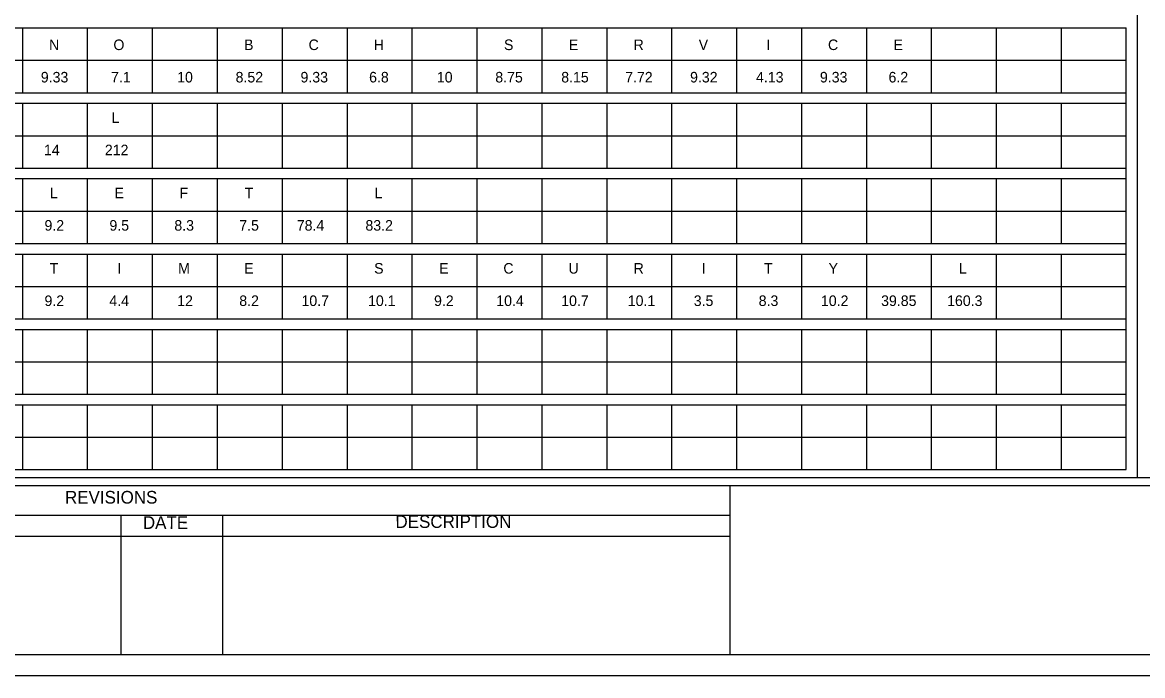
# Model space of a CAD drawing. Extents: x 17890628 to 17890817, y 17897493 to 17897992.
# Drawn here: x 17890684.6 to 17890736.6, y 17897492.8 to 17897523.1 of the extents above; entities that cross this region are included whole.
import ezdxf

# ---------------------------------------------------------------- set-up
doc = ezdxf.new("R2010")
doc.units = 0
for name, color, linetype in [('GSSign', 7, 'Continuous'), ('PlotBorder_dp', 7, 'Continuous'), ('SheetBorder_dp', 7, 'Continuous'), ('SheetLines_dp', 7, 'Continuous'), ('SheetLinesMisc2_dp', 7, 'Continuous'), ('TextMisc', 7, 'Continuous')]:
    doc.layers.add(name, color=color, linetype=linetype)

msp = doc.modelspace()

# ---------------------------------------------------------------- linework, layer by layer
at = {"layer": 'PlotBorder_dp'}
msp.add_lwpolyline([(17890655.57, 17897492.839), (17890817.319, 17897492.839), (17890817.319, 17897596.75), (17890655.57, 17897596.75)], close=True, dxfattribs=at)
at = {"layer": 'SheetBorder_dp'}
for p, q in [((17890660.962, 17897501.661), (17890811.928, 17897501.661)), ((17890660.962, 17897493.819), (17890811.928, 17897493.819))]:
    msp.add_line(p, q, dxfattribs=at)
at = {"layer": 'SheetLines_dp'}
for p, q in [((17890717.427, 17897501.661), (17890717.427, 17897493.819)), ((17890660.962, 17897500.289), (17890717.427, 17897500.289)), ((17890689.194, 17897500.289), (17890689.194, 17897493.819)), ((17890693.9, 17897500.289), (17890693.9, 17897493.819)), ((17890660.962, 17897499.309), (17890717.427, 17897499.309))]:
    msp.add_line(p, q, dxfattribs=at)
at = {"layer": 'SheetLinesMisc2_dp'}
for p, q in [((17890736.311, 17897595.691), (17890736.311, 17897502.033)), ((17890661.804, 17897522.886), (17890735.8, 17897522.886)), ((17890684.628, 17897522.886), (17890684.628, 17897519.88)), ((17890687.638, 17897522.886), (17890687.638, 17897519.88)), ((17890690.648, 17897522.886), (17890690.648, 17897519.88)), ((17890693.658, 17897522.886), (17890693.658, 17897519.88)), ((17890696.669, 17897522.886), (17890696.669, 17897519.88)), ((17890699.679, 17897522.886), (17890699.679, 17897519.88)), ((17890702.689, 17897522.886), (17890702.689, 17897519.88)), ((17890705.699, 17897522.886), (17890705.699, 17897519.88)), ((17890708.709, 17897522.886), (17890708.709, 17897519.88)), ((17890711.719, 17897522.886), (17890711.719, 17897519.88)), ((17890714.729, 17897522.886), (17890714.729, 17897519.88)), ((17890717.739, 17897522.886), (17890717.739, 17897519.88)), ((17890720.749, 17897522.886), (17890720.749, 17897519.88)), ((17890723.759, 17897522.886), (17890723.759, 17897519.88)), ((17890726.769, 17897522.886), (17890726.769, 17897519.88)), ((17890729.779, 17897522.886), (17890729.779, 17897519.88)), ((17890732.79, 17897522.886), (17890732.79, 17897519.88)), ((17890735.8, 17897502.398), (17890735.8, 17897522.886)), ((17890661.804, 17897521.384), (17890735.8, 17897521.384)), ((17890661.804, 17897519.88), (17890735.8, 17897519.88)), ((17890661.804, 17897519.389), (17890735.8, 17897519.389)), ((17890684.628, 17897519.389), (17890684.628, 17897516.383)), ((17890687.638, 17897519.389), (17890687.638, 17897516.383)), ((17890690.648, 17897519.389), (17890690.648, 17897516.383)), ((17890693.658, 17897519.389), (17890693.658, 17897516.383)), ((17890696.669, 17897519.389), (17890696.669, 17897516.383)), ((17890699.679, 17897519.389), (17890699.679, 17897516.383)), ((17890702.689, 17897519.389), (17890702.689, 17897516.383)), ((17890705.699, 17897519.389), (17890705.699, 17897516.383)), ((17890708.709, 17897519.389), (17890708.709, 17897516.383)), ((17890711.719, 17897519.389), (17890711.719, 17897516.383)), ((17890714.729, 17897519.389), (17890714.729, 17897516.383)), ((17890717.739, 17897519.389), (17890717.739, 17897516.383)), ((17890720.749, 17897519.389), (17890720.749, 17897516.383)), ((17890723.759, 17897519.389), (17890723.759, 17897516.383)), ((17890726.769, 17897519.389), (17890726.769, 17897516.383)), ((17890729.779, 17897519.389), (17890729.779, 17897516.383)), ((17890732.79, 17897519.389), (17890732.79, 17897516.383)), ((17890661.804, 17897517.886), (17890735.8, 17897517.886)), ((17890661.804, 17897516.383), (17890735.8, 17897516.383)), ((17890661.804, 17897515.893), (17890735.8, 17897515.893)), ((17890684.628, 17897515.893), (17890684.628, 17897512.887)), ((17890687.638, 17897515.893), (17890687.638, 17897512.887)), ((17890690.648, 17897515.893), (17890690.648, 17897512.887)), ((17890693.658, 17897515.893), (17890693.658, 17897512.887)), ((17890696.669, 17897515.893), (17890696.669, 17897512.887)), ((17890699.679, 17897515.893), (17890699.679, 17897512.887)), ((17890702.689, 17897515.893), (17890702.689, 17897512.887)), ((17890705.699, 17897515.893), (17890705.699, 17897512.887)), ((17890708.709, 17897515.893), (17890708.709, 17897512.887)), ((17890711.719, 17897515.893), (17890711.719, 17897512.887)), ((17890714.729, 17897515.893), (17890714.729, 17897512.887)), ((17890717.739, 17897515.893), (17890717.739, 17897512.887)), ((17890720.749, 17897515.893), (17890720.749, 17897512.887)), ((17890723.759, 17897515.893), (17890723.759, 17897512.887)), ((17890726.769, 17897515.893), (17890726.769, 17897512.887)), ((17890729.779, 17897515.893), (17890729.779, 17897512.887)), ((17890732.79, 17897515.893), (17890732.79, 17897512.887)), ((17890661.804, 17897514.39), (17890735.8, 17897514.39)), ((17890661.804, 17897512.887), (17890735.8, 17897512.887)), ((17890661.804, 17897512.396), (17890735.8, 17897512.396)), ((17890684.628, 17897512.396), (17890684.628, 17897509.39)), ((17890687.638, 17897512.396), (17890687.638, 17897509.39)), ((17890690.648, 17897512.396), (17890690.648, 17897509.39)), ((17890693.658, 17897512.396), (17890693.658, 17897509.39)), ((17890696.669, 17897512.396), (17890696.669, 17897509.39)), ((17890699.679, 17897512.396), (17890699.679, 17897509.39)), ((17890702.689, 17897512.396), (17890702.689, 17897509.39)), ((17890705.699, 17897512.396), (17890705.699, 17897509.39)), ((17890708.709, 17897512.396), (17890708.709, 17897509.39)), ((17890711.719, 17897512.396), (17890711.719, 17897509.39)), ((17890714.729, 17897512.396), (17890714.729, 17897509.39)), ((17890717.739, 17897512.396), (17890717.739, 17897509.39)), ((17890720.749, 17897512.396), (17890720.749, 17897509.39)), ((17890723.759, 17897512.396), (17890723.759, 17897509.39)), ((17890726.769, 17897512.396), (17890726.769, 17897509.39)), ((17890729.779, 17897512.396), (17890729.779, 17897509.39)), ((17890732.79, 17897512.396), (17890732.79, 17897509.39)), ((17890661.804, 17897510.894), (17890735.8, 17897510.894)), ((17890661.804, 17897509.39), (17890735.8, 17897509.39)), ((17890661.804, 17897508.9), (17890735.8, 17897508.9)), ((17890684.628, 17897508.9), (17890684.628, 17897505.894)), ((17890687.638, 17897508.9), (17890687.638, 17897505.894)), ((17890690.648, 17897508.9), (17890690.648, 17897505.894)), ((17890693.658, 17897508.9), (17890693.658, 17897505.894)), ((17890696.669, 17897508.9), (17890696.669, 17897505.894)), ((17890699.679, 17897508.9), (17890699.679, 17897505.894)), ((17890702.689, 17897508.9), (17890702.689, 17897505.894)), ((17890705.699, 17897508.9), (17890705.699, 17897505.894)), ((17890708.709, 17897508.9), (17890708.709, 17897505.894)), ((17890711.719, 17897508.9), (17890711.719, 17897505.894)), ((17890714.729, 17897508.9), (17890714.729, 17897505.894)), ((17890717.739, 17897508.9), (17890717.739, 17897505.894)), ((17890720.749, 17897508.9), (17890720.749, 17897505.894)), ((17890723.759, 17897508.9), (17890723.759, 17897505.894)), ((17890726.769, 17897508.9), (17890726.769, 17897505.894)), ((17890729.779, 17897508.9), (17890729.779, 17897505.894)), ((17890732.79, 17897508.9), (17890732.79, 17897505.894)), ((17890661.804, 17897507.396), (17890735.8, 17897507.396)), ((17890661.804, 17897505.894), (17890735.8, 17897505.894)), ((17890661.804, 17897505.403), (17890735.8, 17897505.403)), ((17890684.628, 17897505.403), (17890684.628, 17897502.398)), ((17890687.638, 17897505.403), (17890687.638, 17897502.398)), ((17890690.648, 17897505.403), (17890690.648, 17897502.398)), ((17890693.658, 17897505.403), (17890693.658, 17897502.398)), ((17890696.669, 17897505.403), (17890696.669, 17897502.398)), ((17890699.679, 17897505.403), (17890699.679, 17897502.398)), ((17890702.689, 17897505.403), (17890702.689, 17897502.398)), ((17890705.699, 17897505.403), (17890705.699, 17897502.398)), ((17890708.709, 17897505.403), (17890708.709, 17897502.398)), ((17890711.719, 17897505.403), (17890711.719, 17897502.398)), ((17890714.729, 17897505.403), (17890714.729, 17897502.398)), ((17890717.739, 17897505.403), (17890717.739, 17897502.398)), ((17890720.749, 17897505.403), (17890720.749, 17897502.398)), ((17890723.759, 17897505.403), (17890723.759, 17897502.398)), ((17890726.769, 17897505.403), (17890726.769, 17897502.398)), ((17890729.779, 17897505.403), (17890729.779, 17897502.398)), ((17890732.79, 17897505.403), (17890732.79, 17897502.398)), ((17890661.804, 17897503.9), (17890735.8, 17897503.9)), ((17890661.804, 17897502.398), (17890735.8, 17897502.398)), ((17890661.083, 17897502.033), (17890811.539, 17897502.033))]:
    msp.add_line(p, q, dxfattribs=at)

# ---------------------------------------------------------------- texts
at = {"layer": 'GSSign'}
for s, height, p in [('N', 0.49, (17890685.865, 17897521.859)), ('O', 0.49, (17890688.848, 17897521.859)), ('B', 0.49, (17890694.904, 17897521.859)), ('C', 0.49, (17890697.898, 17897521.859)), ('H', 0.49, (17890700.917, 17897521.859)), ('S', 0.49, (17890706.958, 17897521.859)), ('E', 0.49, (17890709.968, 17897521.859)), ('R', 0.49, (17890712.966, 17897521.859)), ('V', 0.49, (17890715.986, 17897521.859)), ('I', 0.49, (17890719.13, 17897521.859)), ('C', 0.49, (17890721.981, 17897521.859)), ('E', 0.49, (17890725.019, 17897521.859)), ('9.33', 0.4902, (17890685.482, 17897520.356)), ('7.1', 0.4902, (17890688.737, 17897520.356)), ('10', 0.4902, (17890691.803, 17897520.356)), ('8.52', 0.4902, (17890694.513, 17897520.356)), ('9.33', 0.4902, (17890697.523, 17897520.356)), ('6.8', 0.4902, (17890700.703, 17897520.356)), ('10', 0.4902, (17890703.845, 17897520.356)), ('8.75', 0.4902, (17890706.554, 17897520.356)), ('8.15', 0.4902, (17890709.612, 17897520.356)), ('7.72', 0.4902, (17890712.575, 17897520.356)), ('9.32', 0.4902, (17890715.585, 17897520.356)), ('4.13', 0.4902, (17890718.643, 17897520.356)), ('9.33', 0.4902, (17890721.606, 17897520.356)), ('6.2', 0.4902, (17890724.787, 17897520.356)), ('L', 0.49, (17890688.757, 17897518.481)), ('14', 0.4902, (17890685.628, 17897516.978)), ('212', 0.4902, (17890688.451, 17897516.978)), ('L', 0.49, (17890685.9, 17897514.984)), ('E', 0.49, (17890688.895, 17897514.984)), ('F', 0.49, (17890691.914, 17897514.984)), ('T', 0.49, (17890694.928, 17897514.984)), ('L', 0.49, (17890700.952, 17897514.984)), ('9.2', 0.4902, (17890685.652, 17897513.481)), ('9.5', 0.4902, (17890688.663, 17897513.481)), ('8.3', 0.4902, (17890691.673, 17897513.481)), ('7.5', 0.4902, (17890694.684, 17897513.481)), ('78.4', 0.4902, (17890697.35, 17897513.481)), ('83.2', 0.4902, (17890700.533, 17897513.481)), ('T', 0.49, (17890685.897, 17897511.488)), ('I', 0.49, (17890689.027, 17897511.488)), ('M', 0.49, (17890691.85, 17897511.488)), ('E', 0.49, (17890694.916, 17897511.488)), ('S', 0.49, (17890700.937, 17897511.488)), ('E', 0.49, (17890703.947, 17897511.488)), ('C', 0.49, (17890706.929, 17897511.488)), ('U', 0.49, (17890709.949, 17897511.488)), ('R', 0.49, (17890712.966, 17897511.488)), ('I', 0.49, (17890716.12, 17897511.488)), ('T', 0.49, (17890719.011, 17897511.488)), ('Y', 0.49, (17890722.008, 17897511.488)), ('L', 0.49, (17890728.045, 17897511.488)), ('9.2', 0.4902, (17890685.652, 17897509.985)), ('4.4', 0.4902, (17890688.66, 17897509.985)), ('12', 0.4902, (17890691.806, 17897509.985)), ('8.2', 0.4902, (17890694.683, 17897509.985)), ('10.7', 0.4902, (17890697.568, 17897509.985)), ('10.1', 0.4902, (17890700.654, 17897509.985)), ('9.2', 0.4902, (17890703.714, 17897509.985)), ('10.4', 0.4902, (17890706.599, 17897509.985)), ('10.7', 0.4902, (17890709.61, 17897509.985)), ('10.1', 0.4902, (17890712.696, 17897509.985)), ('3.5', 0.4902, (17890715.756, 17897509.985)), ('8.3', 0.4902, (17890718.767, 17897509.985)), ('10.2', 0.4902, (17890721.653, 17897509.985)), ('39.85', 0.4902, (17890724.443, 17897509.985)), ('160.3', 0.4902, (17890727.503, 17897509.985))]:
    msp.add_text(s, height=height, dxfattribs=at).set_placement(p)
at = {"layer": 'TextMisc'}
msp.add_text('REVISIONS', height=0.5882, dxfattribs=at).set_placement((17890686.603, 17897500.819))
for s, height, rotation, p in [('DATE', 0.5882, 359.8693, (17890690.214, 17897499.645)), ('DESCRIPTION', 0.58818, 0.0498, (17890701.925, 17897499.688))]:
    msp.add_text(s, height=height, rotation=rotation, dxfattribs=at).set_placement(p)

doc.saveas('drawing.dxf')
